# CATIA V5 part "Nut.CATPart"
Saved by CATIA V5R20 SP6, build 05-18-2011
Part number: Nut(M8X1.25)
Bounding box of the stored display mesh (mm): x -8 to 8, y 3.6 to 22.04, z -8 to 0
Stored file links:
  E:\#01 CATIA Lecture Materials\#06 DMU\#05 DMU Page01 KIN EX05\Nut.CATPart
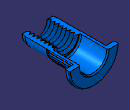
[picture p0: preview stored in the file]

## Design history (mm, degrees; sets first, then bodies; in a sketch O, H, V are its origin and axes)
Body1 (main body)
Body2 "NUT"
  Solid1: solid without history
